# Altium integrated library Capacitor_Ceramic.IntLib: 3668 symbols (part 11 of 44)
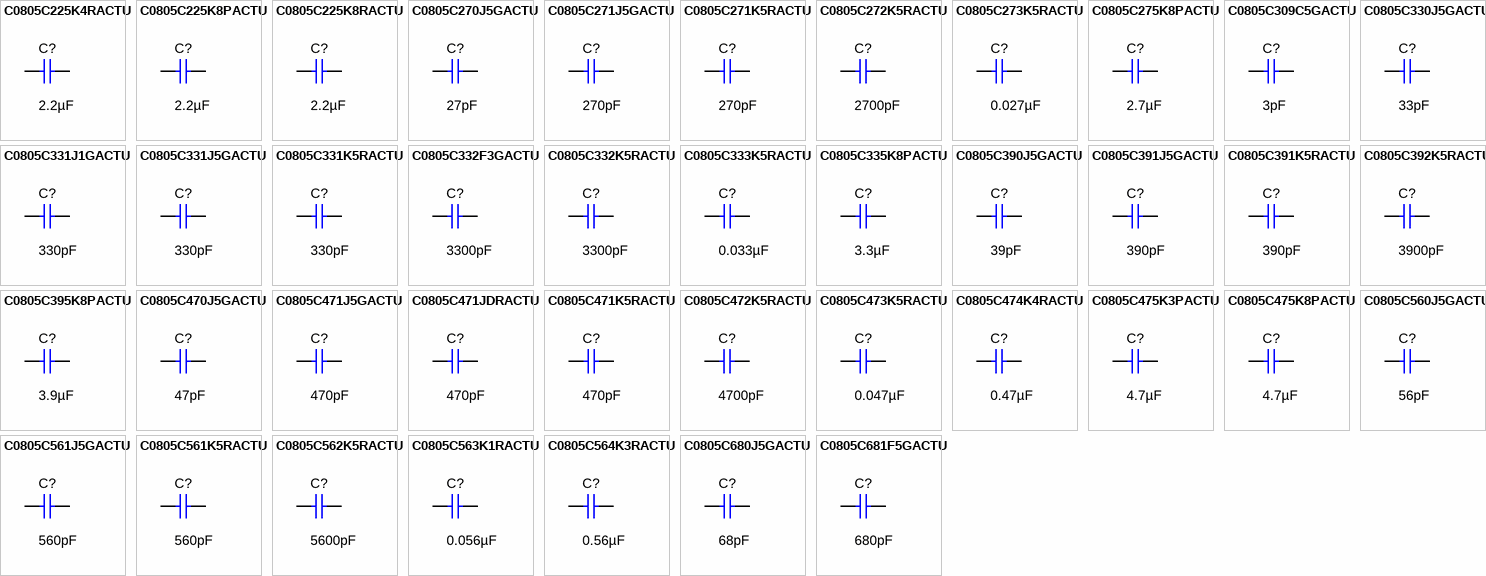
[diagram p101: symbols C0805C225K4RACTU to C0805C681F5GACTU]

## C0805C680J5GACTU
designator C?  ValueDisplayed: 68pF  (hidden comment: C0805C680J5GACTU)
CAP, CERM, 68 pF, 50 V,+/- 5%, C0G/NP0, 0805; Manufacturer: Kemet; Polarized: N; CompType: Capacitor; Value: 68pF; U/M: EA; Cap_F: 0.000000000068; Tolerance_%: 5; ESR_ohm: 0.094; Value1: 0.094 ohm; VDC_V: 50; Value2: 50V; IRMS_A: 0.603; TaMin_C: -55; TaMax_C: 125; Cap_Case: 0805; SizeArea_mm2: 2.5; SizeAreaWB_mm2: 6.75; SizeX_mm: 2; SizeY_mm: 1.25; SizeZ_mm: 1.45; AEC Category: Q200; Green_Lifecycle: Not Set; Green_REACh: Incomplete
signal-integrity model Cap
simulation model Cap
footprint 0805_HV
footprint 0805_HV1
footprint 0805
footprint 0805M
footprint 0805L
pins: 1, 2

## C0805C681F5GACTU
designator C?  ValueDisplayed: 680pF  (hidden comment: C0805C681F5GACTU)
CAP, CERM, 680 pF, 50 V,+/- 1%, C0G/NP0, 0805; Manufacturer: Kemet; Polarized: N; CompType: Capacitor; Value: 680pF; U/M: EA; Cap_F: 0.00000000068; Tolerance_%: 1; VDC_V: 50; Value2: 50V; TaMin_C: -55; TaMax_C: 125; Cap_Case: 0805; SizeArea_mm2: 2.5; SizeAreaWB_mm2: 6.75; SizeX_mm: 2; SizeY_mm: 1.25; SizeZ_mm: 1.45; AEC Category: Q200; Green_Lifecycle: Not Set; Green_REACh: Incomplete
signal-integrity model Cap
simulation model Cap
footprint 0805_HV
footprint 0805_HV1
footprint 0805
footprint 0805M
footprint 0805L
pins: 1, 2

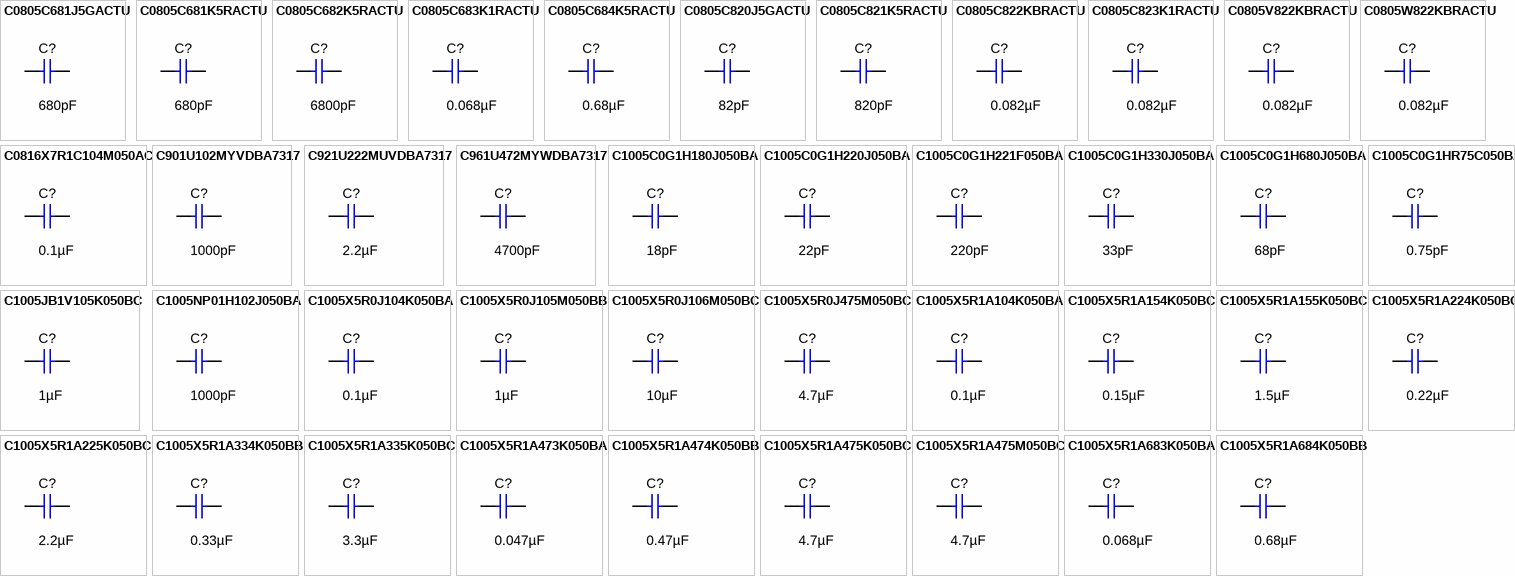
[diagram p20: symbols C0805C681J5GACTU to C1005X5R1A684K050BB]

## C0805C681J5GACTU
designator C?  ValueDisplayed: 680pF  (hidden comment: C0805C681J5GACTU)
CAP, CERM, 680 pF, 50 V,+/- 5%, C0G/NP0, 0805; Manufacturer: Kemet; Polarized: N; CompType: Capacitor; Value: 680pF; U/M: EA; Cap_F: 0.00000000068; Tolerance_%: 5; ESR_ohm: 0.027; Value1: 0.027 ohm; VDC_V: 50; Value2: 50V; IRMS_A: 1.38; TaMin_C: -55; TaMax_C: 125; Cap_Case: 0805; SizeArea_mm2: 2.5; SizeAreaWB_mm2: 6.75; SizeX_mm: 2; SizeY_mm: 1.25; SizeZ_mm: 1.45; AEC Category: Q200; Green_Lifecycle: Not Set; Green_REACh: Incomplete
signal-integrity model Cap
simulation model Cap
footprint 0805_HV
footprint 0805_HV1
footprint 0805
footprint 0805M
footprint 0805L
pins: 1, 2

## C0805C681K5RACTU
designator C?  ValueDisplayed: 680pF  (hidden comment: C0805C681K5RACTU)
CAP, CERM, 680 pF, 50 V,+/- 10%, X7R, 0805; Manufacturer: Kemet; Polarized: N; CompType: Capacitor; Value: 680pF; U/M: EA; Cap_F: 0.00000000068; Tolerance_%: 10; ESR_ohm: 0.478; Value1: 0.478 ohm; VDC_V: 50; Value2: 50V; IRMS_A: 0.188; TaMin_C: -55; TaMax_C: 125; Cap_Case: 0805; SizeArea_mm2: 2.5; SizeAreaWB_mm2: 6.75; SizeX_mm: 2; SizeY_mm: 1.25; SizeZ_mm: 1.45; AEC Category: Q200; Green_Lifecycle: Not Set; Green_REACh: Incomplete
signal-integrity model Cap
simulation model Cap
footprint 0805_HV
footprint 0805_HV1
footprint 0805
footprint 0805M
footprint 0805L
pins: 1, 2

## C0805C682K5RACTU
designator C?  ValueDisplayed: 6800pF  (hidden comment: C0805C682K5RACTU)
CAP, CERM, 6800 pF, 50 V,+/- 10%, X7R, 0805; Manufacturer: Kemet; Polarized: N; CompType: Capacitor; Value: 6800pF; U/M: EA; Cap_F: 0.0000000068; Tolerance_%: 10; ESR_ohm: 0.182; Value1: 0.182 ohm; VDC_V: 50; Value2: 50V; IRMS_A: 0.336; TaMin_C: -55; TaMax_C: 125; Cap_Case: 0805; SizeArea_mm2: 2.5; SizeAreaWB_mm2: 6.75; SizeX_mm: 2; SizeY_mm: 1.25; SizeZ_mm: 1.45; AEC Category: Q200; Green_Lifecycle: Not Set; Green_REACh: Incomplete
signal-integrity model Cap
simulation model Cap
footprint 0805_HV
footprint 0805_HV1
footprint 0805
footprint 0805M
footprint 0805L
pins: 1, 2

## C0805C683K1RACTU
designator C?  ValueDisplayed: 0.068µF  (hidden comment: C0805C683K1RACTU)
CAP, CERM, 0.068 µF, 100 V,+/- 10%, X7R, 0805; Manufacturer: Kemet; Polarized: N; CompType: Capacitor; Value: 0.068uF; U/M: EA; Cap_F: 0.000000068; Tolerance_%: 10; ESR_ohm: 0.078; Value1: 0.078 ohm; VDC_V: 100; Value2: 100V; IRMS_A: 1.28; TaMin_C: -55; TaMax_C: 125; Cap_Case: 0805; SizeArea_mm2: 2.5; SizeAreaWB_mm2: 6.75; SizeX_mm: 2; SizeY_mm: 1.25; SizeZ_mm: 1.45; AEC Category: Q200; Green_Lifecycle: Not Set; Green_REACh: Incomplete
signal-integrity model Cap
simulation model Cap
footprint 0805_HV
footprint 0805_HV1
footprint 0805
footprint 0805M
footprint 0805L
pins: 1, 2

## C0805C684K5RACTU
designator C?  ValueDisplayed: 0.68µF  (hidden comment: C0805C684K5RACTU)
CAP, CERM, 0.68 µF, 50 V,+/- 10%, X7R, 0805; Manufacturer: Kemet; Polarized: N; CompType: Capacitor; Value: 0.68uF; U/M: EA; Cap_F: 0.00000068; Tolerance_%: 10; VDC_V: 50; Value2: 50V; TaMin_C: -55; TaMax_C: 125; Cap_Case: 0805; SizeArea_mm2: 2.5; SizeAreaWB_mm2: 6.75; SizeX_mm: 2; SizeY_mm: 1.25; SizeZ_mm: 1.45; AEC Category: Q200; Green_Lifecycle: Active; Green_REACh: Passed
signal-integrity model Cap
simulation model Cap
footprint 0805_HV
footprint 0805_HV1
footprint 0805
footprint 0805M
footprint 0805L
pins: 1, 2

## C0805C820J5GACTU
designator C?  ValueDisplayed: 82pF  (hidden comment: C0805C820J5GACTU)
CAP, CERM, 82 pF, 50 V,+/- 5%, C0G/NP0, 0805; Manufacturer: Kemet; Polarized: N; CompType: Capacitor; Value: 82pF; U/M: EA; Cap_F: 0.000000000082; Tolerance_%: 5; ESR_ohm: 0.084; Value1: 0.084 ohm; VDC_V: 50; Value2: 50V; IRMS_A: 0.677; TaMin_C: -55; TaMax_C: 125; Cap_Case: 0805; SizeArea_mm2: 2.5; SizeAreaWB_mm2: 6.75; SizeX_mm: 2; SizeY_mm: 1.25; SizeZ_mm: 1.45; AEC Category: Q200; Green_Lifecycle: Active; Green_REACh: Passed
signal-integrity model Cap
simulation model Cap
footprint 0805_HV
footprint 0805_HV1
footprint 0805
footprint 0805M
footprint 0805L
pins: 1, 2

## C0805C821K5RACTU
designator C?  ValueDisplayed: 820pF  (hidden comment: C0805C821K5RACTU)
CAP, CERM, 820 pF, 50 V,+/- 10%, X7R, 0805; Manufacturer: Kemet; Polarized: N; CompType: Capacitor; Value: 820pF; U/M: EA; Cap_F: 0.00000000082; Tolerance_%: 10; ESR_ohm: 0.425; Value1: 0.425 ohm; VDC_V: 50; Value2: 50V; IRMS_A: 0.204; TaMin_C: -55; TaMax_C: 125; Cap_Case: 0805; SizeArea_mm2: 2.5; SizeAreaWB_mm2: 6.75; SizeX_mm: 2; SizeY_mm: 1.25; SizeZ_mm: 1.45; AEC Category: Q200; Green_Lifecycle: Not Set; Green_REACh: Incomplete
signal-integrity model Cap
simulation model Cap
footprint 0805_HV
footprint 0805_HV1
footprint 0805
footprint 0805M
footprint 0805L
pins: 1, 2

## C0805C822KBRACTU
designator C?  ValueDisplayed: 0.082µF  (hidden comment: C0805C822KBRACTU)
CAP, CERM, 0.082 µF, 630 V,+/- 10%, X7R, 0805; Manufacturer: Kemet; Polarized: N; CompType: Capacitor; Value: 0.082uF; U/M: EA; Cap_F: 0.000000082; Tolerance_%: 10; VDC_V: 630; Value2: 630V; TaMin_C: -55; TaMax_C: 125; Cap_Case: 0805; SizeArea_mm2: 2.5; SizeAreaWB_mm2: 6.75; SizeX_mm: 2; SizeY_mm: 1.25; SizeZ_mm: 1.45; AEC Category: Q200; Green_Lifecycle: Not Set; Green_REACh: Incomplete
signal-integrity model Cap
simulation model Cap
footprint 0805_HV
footprint 0805_HV1
footprint 0805
footprint 0805M
footprint 0805L
pins: 1, 2

## C0805C823K1RACTU
designator C?  ValueDisplayed: 0.082µF  (hidden comment: C0805C823K1RACTU)
CAP, CERM, 0.082 µF, 100 V,+/- 10%, X7R, 0805; Manufacturer: Kemet; Polarized: N; CompType: Capacitor; Value: 0.082uF; U/M: EA; Cap_F: 0.000000082; Tolerance_%: 10; ESR_ohm: 0.071; Value1: 0.071 ohm; VDC_V: 100; Value2: 100V; IRMS_A: 1.44; TaMin_C: -55; TaMax_C: 125; Cap_Case: 0805; SizeArea_mm2: 2.5; SizeAreaWB_mm2: 6.75; SizeX_mm: 2; SizeY_mm: 1.25; SizeZ_mm: 1.45; AEC Category: Q200; Green_Lifecycle: Not Set; Green_REACh: Incomplete
signal-integrity model Cap
simulation model Cap
footprint 0805_HV
footprint 0805_HV1
footprint 0805
footprint 0805M
footprint 0805L
pins: 1, 2

## C0805V822KBRACTU
designator C?  ValueDisplayed: 0.082µF  (hidden comment: C0805V822KBRACTU)
CAP, CERM, 0.082 µF, 630 V,+/- 10%, X7R, 0805; Manufacturer: Kemet; Polarized: N; CompType: Capacitor; Value: 0.082uF; U/M: EA; Cap_F: 0.000000082; Tolerance_%: 10; VDC_V: 630; Value2: 630V; TaMin_C: -55; TaMax_C: 125; Cap_Case: 0805; SizeArea_mm2: 2.5; SizeAreaWB_mm2: 6.75; SizeX_mm: 2; SizeY_mm: 1.25; SizeZ_mm: 1.45; AEC Category: Q200; Green_Lifecycle: Not Set; Green_REACh: Incomplete
signal-integrity model Cap
simulation model Cap
footprint 0805_HV
footprint 0805_HV1
footprint 0805
footprint 0805M
footprint 0805L
pins: 1, 2

## C0805W822KBRACTU
designator C?  ValueDisplayed: 0.082µF  (hidden comment: C0805W822KBRACTU)
CAP, CERM, 0.082 µF, 630 V,+/- 10%, X7R, 0805; Manufacturer: Kemet; Polarized: N; CompType: Capacitor; Value: 0.082uF; U/M: EA; Cap_F: 0.000000082; Tolerance_%: 10; VDC_V: 630; Value2: 630V; TaMin_C: -55; TaMax_C: 125; Cap_Case: 0805; SizeArea_mm2: 2.5; SizeAreaWB_mm2: 6.75; SizeX_mm: 2; SizeY_mm: 1.25; SizeZ_mm: 1.45; AEC Category: Q200; Green_Lifecycle: Not Set; Green_REACh: Incomplete
signal-integrity model Cap
simulation model Cap
footprint 0805_HV
footprint 0805_HV1
footprint 0805
footprint 0805M
footprint 0805L
pins: 1, 2

## C0816X7R1C104M050AC
designator C?  ValueDisplayed: 0.1µF  (hidden comment: C0816X7R1C104M050AC)
CAP, CERM, 0.1 µF, 16 V,+/- 20%, X7R, 0306; Manufacturer: TDK; Polarized: N; CompType: Capacitor; Value: 0.1uF; U/M: EA; Cap_F: 0.0000001; Tolerance_%: 20; VDC_V: 16; Value2: 16V; TaMin_C: -55; TaMax_C: 125; Cap_Case: 0306; SizeArea_mm2: 1.28; SizeAreaWB_mm2: 4.68; SizeX_mm: 0.8; SizeY_mm: 1.6; SizeZ_mm: 0.6; AEC Category: Q200; Green_Lifecycle: Not Set; Green_REACh: Incomplete
signal-integrity model Cap
simulation model Cap
footprint 0306
pins: 1, 2

## C901U102MYVDBA7317
designator C?  ValueDisplayed: 1000pF  (hidden comment: C901U102MYVDBA7317)
CAP, CERM, 1000 pF, X1 400 VAC/Y2 250 VAC, +/- 20%, Y5V, D7xT5mm; Manufacturer: Kemet; Polarized: N; CompType: Capacitor; Value: 1000pF; U/M: EA; Cap_F: 0.000000001; Tolerance_%: 20; TaMin_C: -40; TaMax_C: 125; Cap_Case: 7x5mm; SizeArea_mm2: 55; SizeAreaWB_mm2: 91; SizeX_mm: 11; SizeY_mm: 5; AEC Category: Q200; Green_Lifecycle: Not Set; Green_REACh: Incomplete; AC_Safety: X1Y2; VAC_X: 400; VAC_Y: 250
signal-integrity model Cap
simulation model Cap
footprint C901_B
pins: 1, 2

## C921U222MUVDBA7317
designator C?  ValueDisplayed: 2.2µF  (hidden comment: C921U222MUVDBA7317)
CAP, CERM, 2.2 µF, X1 400 VAC/Y1 250 VAC, +/- 20%, Y5V, Cap 9x13mm; Manufacturer: Kemet; Polarized: N; CompType: Capacitor; Value: 2.2uF; U/M: EA; Cap_F: 0.0000022; Tolerance_%: 20; TaMin_C: -25; TaMax_C: 125; Cap_Case: C921_5500T_VertKink; SizeArea_mm2: 45; SizeAreaWB_mm2: 77; SizeX_mm: 9; SizeY_mm: 5; SizeZ_mm: 14; AEC Category: Q200; AC_Safety: X1Y1; VAC_X: 400; VAC_Y: 250
signal-integrity model Cap
simulation model Cap
footprint C921_5500T_VertKink
pins: 1, 2

## C961U472MYWDBA7317
designator C?  ValueDisplayed: 4700pF  (hidden comment: C961U472MYWDBA7317)
CAP, CERM, 4700 pF, X1 400 VAC/Y2 250 VAC, +/- 20%, Y5U, 13x5mm; Manufacturer: Kemet; Polarized: N; CompType: Capacitor; Value: 4700pF; U/M: EA; Cap_F: 0.0000000047; Tolerance_%: 20; TaMin_C: -40; TaMax_C: 125; SizeArea_mm2: 65; SizeAreaWB_mm2: 105; SizeX_mm: 13; SizeY_mm: 5; SizeZ_mm: 17; AEC Category: Q200; AC_Safety: X1Y2; VAC_X: 400; VAC_Y: 250
signal-integrity model Cap
simulation model Cap
footprint C961_B
pins: 1, 2

## C1005C0G1H180J050BA
designator C?  ValueDisplayed: 18pF  (hidden comment: C1005C0G1H180J050BA)
CAP, CERM, 18 pF, 50 V,+/- 5%, C0G/NP0, 0402; Manufacturer: TDK; Polarized: N; CompType: Capacitor; Value: 18pF; U/M: EA; Cap_F: 0.000000000018; Tolerance_%: 5; VDC_V: 50; Value2: 50V; TaMin_C: -55; TaMax_C: 125; Cap_Case: 0402; SizeArea_mm2: 0.5; SizeAreaWB_mm2: 3; SizeX_mm: 1; SizeZ_mm: 0.6; AEC Category: Q200; Green_Lifecycle: Not Set; Green_REACh: Incomplete
signal-integrity model Cap
simulation model Cap
footprint 0402
footprint 0402M
footprint 0402L
footprint 0402S
pins: 1, 2

## C1005C0G1H220J050BA
designator C?  ValueDisplayed: 22pF  (hidden comment: C1005C0G1H220J050BA)
CAP, CERM, 22 pF, 50 V,+/- 5%, C0G/NP0, 0402; Manufacturer: TDK; Polarized: N; CompType: Capacitor; Value: 22pF; U/M: EA; Cap_F: 0.000000000022; Tolerance_%: 5; VDC_V: 50; Value2: 50V; TaMin_C: -55; TaMax_C: 125; Cap_Case: 0402; SizeArea_mm2: 0.5; SizeAreaWB_mm2: 3; SizeX_mm: 1; SizeZ_mm: 0.6; AEC Category: Q200; Green_Lifecycle: NRND; Green_REACh: Passed
signal-integrity model Cap
simulation model Cap
footprint 0402
footprint 0402M
footprint 0402L
footprint 0402S
pins: 1, 2

## C1005C0G1H221F050BA
designator C?  ValueDisplayed: 220pF  (hidden comment: C1005C0G1H221F050BA)
CAP, CERM, 220 pF, 50 V,+/- 1%, C0G/NP0, 0402; Manufacturer: TDK; Polarized: N; CompType: Capacitor; Value: 220pF; U/M: EA; Cap_F: 0.00000000022; Tolerance_%: 1; VDC_V: 50; Value2: 50V; TaMin_C: -55; TaMax_C: 125; Cap_Case: 0402; SizeArea_mm2: 0.5; SizeAreaWB_mm2: 3; SizeZ_mm: 0.6; AEC Category: Q200; Green_Lifecycle: NRND; Green_REACh: Passed
signal-integrity model Cap
simulation model Cap
footprint 0402
footprint 0402M
footprint 0402L
footprint 0402S
pins: 1, 2

## C1005C0G1H330J050BA
designator C?  ValueDisplayed: 33pF  (hidden comment: C1005C0G1H330J050BA)
CAP, CERM, 33 pF, 50 V,+/- 5%, C0G/NP0, 0402; Manufacturer: TDK; Polarized: N; CompType: Capacitor; Value: 33pF; U/M: EA; Cap_F: 0.000000000033; Tolerance_%: 5; VDC_V: 50; Value2: 50V; TaMin_C: -55; TaMax_C: 125; Cap_Case: 0402; SizeArea_mm2: 0.5; SizeAreaWB_mm2: 3; SizeX_mm: 1; SizeZ_mm: 0.6; AEC Category: Q200; Green_Lifecycle: Not Set; Green_REACh: Incomplete
signal-integrity model Cap
simulation model Cap
footprint 0402
footprint 0402M
footprint 0402L
footprint 0402S
pins: 1, 2

## C1005C0G1H680J050BA
designator C?  ValueDisplayed: 68pF  (hidden comment: C1005C0G1H680J050BA)
CAP, CERM, 68 pF, 50 V,+/- 5%, C0G/NP0, 0402; Manufacturer: TDK; Polarized: N; CompType: Capacitor; Value: 68pF; U/M: EA; Cap_F: 0.000000000068; Tolerance_%: 5; VDC_V: 50; Value2: 50V; TaMin_C: -55; TaMax_C: 125; Cap_Case: 0402; SizeArea_mm2: 0.5; SizeAreaWB_mm2: 3; SizeX_mm: 1; SizeZ_mm: 0.6; AEC Category: Q200; Green_Lifecycle: Not Set; Green_REACh: Incomplete
signal-integrity model Cap
simulation model Cap
footprint 0402
footprint 0402M
footprint 0402L
footprint 0402S
pins: 1, 2

## C1005C0G1HR75C050BA
designator C?  ValueDisplayed: 0.75pF  (hidden comment: C1005C0G1HR75C050BA)
CAP, CERM, 0.75pF, 50 V,+/- 33%, C0G/NP0, 0402; Manufacturer: TDK; Polarized: N; CompType: Capacitor; U/M: EA; Cap_F: 0.00000000000075; Tolerance_%: 33; VDC_V: 50; Value2: 50V; TaMin_C: -55; TaMax_C: 125; Cap_Case: 0402; SizeArea_mm2: 0.5; SizeAreaWB_mm2: 3; SizeX_mm: 1; SizeZ_mm: 0.6; AEC Category: Q200
signal-integrity model Cap
simulation model Cap
footprint 0402
footprint 0402M
footprint 0402L
footprint 0402S
pins: 1, 2

## C1005JB1V105K050BC
designator C?  ValueDisplayed: 1µF  (hidden comment: C1005JB1V105K050BC)
CAP, CERM, 1 µF, 35 V,+/- 10%, JB, 0402; Manufacturer: TDK; Polarized: N; CompType: Capacitor; Value: 1uF; U/M: EA; Cap_F: 0.000001; Tolerance_%: 10; VDC_V: 35; Value2: 35V; TaMin_C: -25; TaMax_C: 85; Cap_Case: 0402; SizeArea_mm2: 0.5; SizeAreaWB_mm2: 3; SizeX_mm: 1; SizeZ_mm: 0.6; AEC Category: Q200; Green_Lifecycle: Active; Green_REACh: Passed
signal-integrity model Cap
simulation model Cap
footprint 0402
footprint 0402M
footprint 0402L
footprint 0402S
pins: 1, 2

## C1005NP01H102J050BA
designator C?  ValueDisplayed: 1000pF  (hidden comment: C1005NP01H102J050BA)
CAP, CERM, 1000 pF, 50 V,+/- 5%, C0G/NP0, 0402; Manufacturer: TDK; Polarized: N; CompType: Capacitor; Value: 1000pF; U/M: EA; Cap_F: 0.000000001; Tolerance_%: 5; VDC_V: 50; Value2: 50V; TaMin_C: -55; TaMax_C: 150; Cap_Case: 0402; SizeArea_mm2: 0.5; SizeAreaWB_mm2: 3; SizeX_mm: 1; SizeZ_mm: 0.6; AEC Category: Q200; Green_Lifecycle: Not Set; Green_REACh: Incomplete
signal-integrity model Cap
simulation model Cap
footprint 0402
footprint 0402M
footprint 0402L
footprint 0402S
pins: 1, 2

## C1005X5R0J104K050BA
designator C?  ValueDisplayed: 0.1µF  (hidden comment: C1005X5R0J104K050BA)
CAP, CERM, 0.1 µF, 6.3 V,+/- 10%, X5R, 0402; Manufacturer: TDK; Polarized: N; CompType: Capacitor; Value: 0.1uF; U/M: EA; Cap_F: 0.0000001; Tolerance_%: 10; ESR_ohm: 0.0186; Value1: 0.0186 ohm; VDC_V: 6.3; Value2: 6.3V; TaMin_C: -55; TaMax_C: 85; Cap_Case: 0402; SizeArea_mm2: 0.5; SizeAreaWB_mm2: 3; SizeX_mm: 1; SizeZ_mm: 0.6; AEC Category: Q200; Green_Lifecycle: NRND; Green_REACh: Passed
signal-integrity model Cap
simulation model Cap
footprint 0402
footprint 0402M
footprint 0402L
footprint 0402S
pins: 1, 2

## C1005X5R0J105M050BB
designator C?  ValueDisplayed: 1µF  (hidden comment: C1005X5R0J105M050BB)
CAP, CERM, 1 µF, 6.3 V,+/- 20%, X5R, 0402; Manufacturer: TDK; Polarized: N; CompType: Capacitor; Value: 1uF; U/M: EA; Cap_F: 0.000001; Tolerance_%: 20; ESR_ohm: 0.0079; Value1: 0.0079 ohm; VDC_V: 6.3; Value2: 6.3V; TaMin_C: -55; TaMax_C: 85; Cap_Case: 0402; SizeArea_mm2: 0.5; SizeAreaWB_mm2: 3; SizeX_mm: 1; SizeZ_mm: 0.6; AEC Category: Q200; Green_Lifecycle: EOL; Green_REACh: Passed
signal-integrity model Cap
simulation model Cap
footprint 0402
footprint 0402M
footprint 0402L
footprint 0402S
pins: 1, 2

## C1005X5R0J106M050BC
designator C?  ValueDisplayed: 10µF  (hidden comment: C1005X5R0J106M050BC)
CAP, CERM, 10 µF, 6.3 V,+/- 20%, X5R, 0402; Manufacturer: TDK; Polarized: N; CompType: Capacitor; Value: 10uF; U/M: EA; Cap_F: 0.00001; Tolerance_%: 20; ESR_ohm: 0.003019; Value1: 0.003019 ohm; VDC_V: 6.3; Value2: 6.3V; IRMS_A: 2.87803; TaMin_C: -55; TaMax_C: 85; Cap_Case: 0402; SizeArea_mm2: 0.5; SizeAreaWB_mm2: 3; SizeX_mm: 1; SizeZ_mm: 0.7; AEC Category: Q200; Green_Lifecycle: Active; Green_REACh: Passed
signal-integrity model Cap
simulation model Cap
footprint 0402_070
pins: 1, 2

## C1005X5R0J475M050BC
designator C?  ValueDisplayed: 4.7µF  (hidden comment: C1005X5R0J475M050BC)
CAP, CERM, 4.7 µF, 6.3 V,+/- 20%, X5R, 0402; Manufacturer: TDK; Polarized: N; CompType: Capacitor; Value: 4.7uF; U/M: EA; Cap_F: 0.0000047; Tolerance_%: 20; VDC_V: 6.3; Value2: 6.3V; TaMin_C: -55; TaMax_C: 85; Cap_Case: 0402; SizeArea_mm2: 0.5; SizeAreaWB_mm2: 3; SizeX_mm: 1; SizeZ_mm: 0.6; AEC Category: Q200; Green_Lifecycle: Active; Green_REACh: Passed
signal-integrity model Cap
simulation model Cap
footprint 0402
footprint 0402M
footprint 0402L
footprint 0402S
pins: 1, 2

## C1005X5R1A104K050BA
designator C?  ValueDisplayed: 0.1µF  (hidden comment: C1005X5R1A104K050BA)
CAP, CERM, 0.1 µF, 10 V,+/- 10%, X5R, 0402; Manufacturer: TDK; Polarized: N; CompType: Capacitor; Value: 0.1uF; U/M: EA; Cap_F: 0.0000001; Tolerance_%: 10; Value2: 10V; TaMin_C: -55; TaMax_C: 85; Cap_Case: 0402; SizeArea_mm2: 0.5; SizeAreaWB_mm2: 3; SizeX_mm: 1; SizeZ_mm: 0.6; AEC Category: Q200; Green_Lifecycle: NRND; Green_REACh: Passed
signal-integrity model Cap
simulation model Cap
footprint 0402
footprint 0402M
footprint 0402L
footprint 0402S
pins: 1, 2

## C1005X5R1A154K050BC
designator C?  ValueDisplayed: 0.15µF  (hidden comment: C1005X5R1A154K050BC)
CAP, CERM, 0.15 µF, 10 V,+/- 10%, X5R, 0402; Manufacturer: TDK; Polarized: N; CompType: Capacitor; Value: 0.15uF; U/M: EA; Cap_F: 0.00000015; Tolerance_%: 10; Value2: 10V; TaMin_C: -55; TaMax_C: 85; Cap_Case: 0402; SizeArea_mm2: 0.5; SizeAreaWB_mm2: 3; SizeX_mm: 1; SizeZ_mm: 0.6; AEC Category: Q200; Green_Lifecycle: EOL; Green_REACh: Passed
signal-integrity model Cap
simulation model Cap
footprint 0402
footprint 0402M
footprint 0402L
footprint 0402S
pins: 1, 2

## C1005X5R1A155K050BC
designator C?  ValueDisplayed: 1.5µF  (hidden comment: C1005X5R1A155K050BC)
CAP, CERM, 1.5 µF, 10 V,+/- 10%, X5R, 0402; Manufacturer: TDK; Polarized: N; CompType: Capacitor; Value: 1.5uF; U/M: EA; Cap_F: 0.0000015; Tolerance_%: 10; Value2: 10V; TaMin_C: -55; TaMax_C: 85; Cap_Case: 0402; SizeArea_mm2: 0.5; SizeAreaWB_mm2: 3; SizeX_mm: 1; SizeZ_mm: 0.6; AEC Category: Q200; Green_Lifecycle: Active; Green_REACh: Passed
signal-integrity model Cap
simulation model Cap
footprint 0402
footprint 0402M
footprint 0402L
footprint 0402S
pins: 1, 2

## C1005X5R1A224K050BC
designator C?  ValueDisplayed: 0.22µF  (hidden comment: C1005X5R1A224K050BC)
CAP, CERM, 0.22 µF, 10 V,+/- 10%, X5R, 0402; Manufacturer: TDK; Polarized: N; CompType: Capacitor; Value: 0.22uF; U/M: EA; Cap_F: 0.00000022; Tolerance_%: 10; Value2: 10V; TaMin_C: -55; TaMax_C: 85; Cap_Case: 0402; SizeArea_mm2: 0.5; SizeAreaWB_mm2: 3; SizeX_mm: 1; SizeZ_mm: 0.6; AEC Category: Q200
signal-integrity model Cap
simulation model Cap
footprint 0402
footprint 0402M
footprint 0402L
footprint 0402S
pins: 1, 2

## C1005X5R1A225K050BC
designator C?  ValueDisplayed: 2.2µF  (hidden comment: C1005X5R1A225K050BC)
CAP, CERM, 2.2 µF, 10 V,+/- 10%, X5R, 0402; Manufacturer: TDK; Polarized: N; CompType: Capacitor; Value: 2.2uF; U/M: EA; Cap_F: 0.0000022; Tolerance_%: 10; Value2: 10V; TaMin_C: -55; TaMax_C: 85; Cap_Case: 0402; SizeArea_mm2: 0.5; SizeAreaWB_mm2: 3; SizeX_mm: 1; SizeZ_mm: 0.6; AEC Category: Q200; Green_Lifecycle: Active; Green_REACh: Passed
signal-integrity model Cap
simulation model Cap
footprint 0402
footprint 0402M
footprint 0402L
footprint 0402S
pins: 1, 2

## C1005X5R1A334K050BB
designator C?  ValueDisplayed: 0.33µF  (hidden comment: C1005X5R1A334K050BB)
CAP, CERM, 0.33 µF, 10 V,+/- 10%, X5R, 0402; Manufacturer: TDK; Polarized: N; CompType: Capacitor; Value: 0.33uF; U/M: EA; Cap_F: 0.00000033; Tolerance_%: 10; Value2: 10V; TaMin_C: -55; TaMax_C: 85; Cap_Case: 0402; SizeArea_mm2: 0.5; SizeAreaWB_mm2: 3; SizeX_mm: 1; SizeZ_mm: 0.6; AEC Category: Q200; Green_Lifecycle: EOL; Green_REACh: Passed
signal-integrity model Cap
simulation model Cap
footprint 0402
footprint 0402M
footprint 0402L
footprint 0402S
pins: 1, 2

## C1005X5R1A335K050BC
designator C?  ValueDisplayed: 3.3µF  (hidden comment: C1005X5R1A335K050BC)
CAP, CERM, 3.3 µF, 10 V,+/- 10%, X5R, 0402; Manufacturer: TDK; Polarized: N; CompType: Capacitor; Value: 3.3uF; U/M: EA; Cap_F: 0.0000033; Tolerance_%: 10; ESR_ohm: 0.004157; Value1: 0.004157 ohm; Value2: 10V; IRMS_A: 2.45391; TaMin_C: -55; TaMax_C: 85; Cap_Case: 0402; SizeArea_mm2: 0.5; SizeAreaWB_mm2: 3; SizeX_mm: 1; SizeZ_mm: 0.6; AEC Category: Q200
signal-integrity model Cap
simulation model Cap
footprint 0402
footprint 0402M
footprint 0402L
footprint 0402S
pins: 1, 2

## C1005X5R1A473K050BA
designator C?  ValueDisplayed: 0.047µF  (hidden comment: C1005X5R1A473K050BA)
CAP, CERM, 0.047 µF, 10 V,+/- 10%, X5R, 0402; Manufacturer: TDK; Polarized: N; CompType: Capacitor; Value: 0.047uF; U/M: EA; Cap_F: 0.000000047; Tolerance_%: 10; Value2: 10V; TaMin_C: -55; TaMax_C: 85; Cap_Case: 0402; SizeArea_mm2: 0.5; SizeAreaWB_mm2: 3; SizeX_mm: 1; SizeZ_mm: 0.6; AEC Category: Q200; Green_Lifecycle: NRND; Green_REACh: Passed
signal-integrity model Cap
simulation model Cap
footprint 0402
footprint 0402M
footprint 0402L
footprint 0402S
pins: 1, 2

## C1005X5R1A474K050BB
designator C?  ValueDisplayed: 0.47µF  (hidden comment: C1005X5R1A474K050BB)
CAP, CERM, 0.47 µF, 10 V,+/- 10%, X5R, 0402; Manufacturer: TDK; Polarized: N; CompType: Capacitor; Value: 0.47uF; U/M: EA; Cap_F: 0.00000047; Tolerance_%: 10; Value2: 10V; TaMin_C: -55; TaMax_C: 85; Cap_Case: 0402; SizeArea_mm2: 0.5; SizeAreaWB_mm2: 3; SizeX_mm: 1; SizeZ_mm: 0.6; AEC Category: Q200; Green_Lifecycle: EOL; Green_REACh: Passed
signal-integrity model Cap
simulation model Cap
footprint 0402
footprint 0402M
footprint 0402L
footprint 0402S
pins: 1, 2

## C1005X5R1A475K050BC
designator C?  ValueDisplayed: 4.7µF  (hidden comment: C1005X5R1A475K050BC)
CAP, CERM, 4.7 µF, 10 V,+/- 10%, X5R, 0402; Manufacturer: TDK; Polarized: N; CompType: Capacitor; Value: 4.7uF; U/M: EA; Cap_F: 0.0000047; Tolerance_%: 10; ESR_ohm: 0.003417; Value1: 0.003417 ohm; Value2: 10V; IRMS_A: 2.7063; TaMin_C: -55; TaMax_C: 85; Cap_Case: 0402; SizeArea_mm2: 0.5; SizeAreaWB_mm2: 3; SizeX_mm: 1; SizeZ_mm: 0.65; AEC Category: Q200; Green_Lifecycle: Active; Green_REACh: Passed
signal-integrity model Cap
simulation model Cap
footprint 0402_065
footprint 0402_065M
footprint 0402_065L
footprint 0402_065S
pins: 1, 2

## C1005X5R1A475M050BC
designator C?  ValueDisplayed: 4.7µF  (hidden comment: C1005X5R1A475M050BC)
CAP, CERM, 4.7 µF, 10 V,+/- 20%, X5R, 0402; Manufacturer: TDK; Polarized: N; CompType: Capacitor; Value: 4.7uF; U/M: EA; Cap_F: 0.0000047; Tolerance_%: 20; VDC_V: 10; Value2: 10V; TaMin_C: -55; TaMax_C: 85; Cap_Case: 0402; SizeArea_mm2: 0.5; SizeAreaWB_mm2: 3; SizeX_mm: 1; SizeZ_mm: 0.6; AEC Category: Q200; Green_Lifecycle: Active; Green_REACh: Passed
signal-integrity model Cap
simulation model Cap
footprint 0402
footprint 0402M
footprint 0402L
footprint 0402S
pins: 1, 2

## C1005X5R1A683K050BA
designator C?  ValueDisplayed: 0.068µF  (hidden comment: C1005X5R1A683K050BA)
CAP, CERM, 0.068 µF, 10 V,+/- 10%, X5R, 0402; Manufacturer: TDK; Polarized: N; CompType: Capacitor; Value: 0.068uF; U/M: EA; Cap_F: 0.000000068; Tolerance_%: 10; Value2: 10V; TaMin_C: -55; TaMax_C: 85; Cap_Case: 0402; SizeArea_mm2: 0.5; SizeAreaWB_mm2: 3; SizeX_mm: 1; SizeZ_mm: 0.6; AEC Category: Q200
signal-integrity model Cap
simulation model Cap
footprint 0402
footprint 0402M
footprint 0402L
footprint 0402S
pins: 1, 2

## C1005X5R1A684K050BB
designator C?  ValueDisplayed: 0.68µF  (hidden comment: C1005X5R1A684K050BB)
CAP, CERM, 0.68 µF, 10 V,+/- 10%, X5R, 0402; Manufacturer: TDK; Polarized: N; CompType: Capacitor; Value: 0.68uF; U/M: EA; Cap_F: 0.00000068; Tolerance_%: 10; Value2: 10V; TaMin_C: -55; TaMax_C: 85; Cap_Case: 0402; SizeArea_mm2: 0.5; SizeAreaWB_mm2: 3; SizeX_mm: 1; SizeZ_mm: 0.6; AEC Category: Q200
signal-integrity model Cap
simulation model Cap
footprint 0402
footprint 0402M
footprint 0402L
footprint 0402S
pins: 1, 2

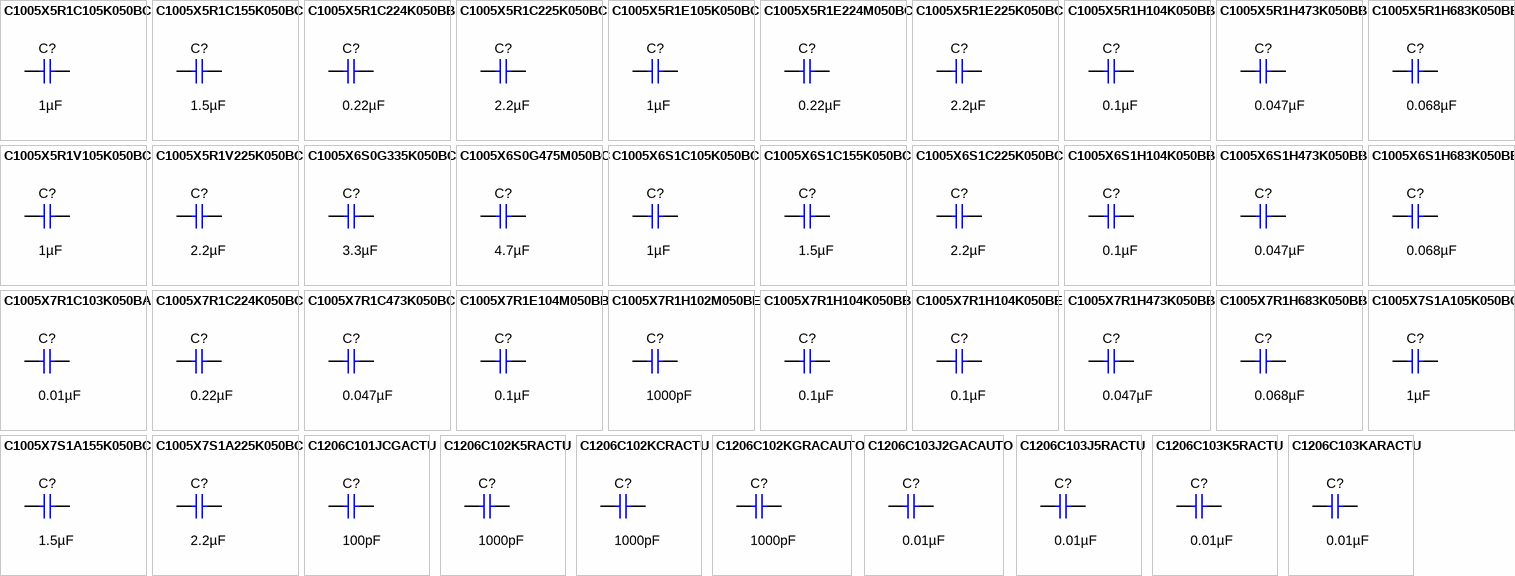
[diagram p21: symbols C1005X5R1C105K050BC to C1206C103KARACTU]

## C1005X5R1C105K050BC
designator C?  ValueDisplayed: 1µF  (hidden comment: C1005X5R1C105K050BC)
CAP, CERM, 1 µF, 16 V,+/- 10%, X5R, 0402; Manufacturer: TDK; Polarized: N; CompType: Capacitor; Value: 1uF; U/M: EA; Cap_F: 0.000001; Tolerance_%: 10; VDC_V: 16; Value2: 16V; TaMin_C: -55; TaMax_C: 85; Cap_Case: 0402; SizeArea_mm2: 0.5; SizeAreaWB_mm2: 3; SizeX_mm: 1; SizeZ_mm: 0.6; AEC Category: Q200; Green_Lifecycle: EOL; Green_REACh: Passed
signal-integrity model Cap
simulation model Cap
footprint 0402
footprint 0402M
footprint 0402L
footprint 0402S
pins: 1, 2

## C1005X5R1C155K050BC
designator C?  ValueDisplayed: 1.5µF  (hidden comment: C1005X5R1C155K050BC)
CAP, CERM, 1.5 µF, 16 V,+/- 10%, X5R, 0402; Manufacturer: TDK; Polarized: N; CompType: Capacitor; Value: 1.5uF; U/M: EA; Cap_F: 0.0000015; Tolerance_%: 10; ESR_ohm: 0.007753; Value1: 0.007753 ohm; VDC_V: 16; Value2: 16V; IRMS_A: 1.79804; TaMin_C: -55; TaMax_C: 85; Cap_Case: 0402; SizeArea_mm2: 0.5; SizeAreaWB_mm2: 3; SizeX_mm: 1; SizeZ_mm: 0.6; AEC Category: Q200
signal-integrity model Cap
simulation model Cap
footprint 0402
footprint 0402M
footprint 0402L
footprint 0402S
pins: 1, 2

## C1005X5R1C224K050BB
designator C?  ValueDisplayed: 0.22µF  (hidden comment: C1005X5R1C224K050BB)
CAP, CERM, 0.22 µF, 16 V,+/- 10%, X5R, 0402; Manufacturer: TDK; Polarized: N; CompType: Capacitor; Value: 0.22uF; U/M: EA; Cap_F: 0.00000022; Tolerance_%: 10; VDC_V: 16; Value2: 16V; TaMin_C: -55; TaMax_C: 85; Cap_Case: 0402; SizeArea_mm2: 0.5; SizeAreaWB_mm2: 3; SizeX_mm: 1; SizeZ_mm: 0.6; AEC Category: Q200; Green_Lifecycle: Not Set; Green_REACh: Incomplete
signal-integrity model Cap
simulation model Cap
footprint 0402
footprint 0402M
footprint 0402L
footprint 0402S
pins: 1, 2

## C1005X5R1C225K050BC
designator C?  ValueDisplayed: 2.2µF  (hidden comment: C1005X5R1C225K050BC)
CAP, CERM, 2.2 µF, 16 V,+/- 10%, X5R, 0402; Manufacturer: TDK; Polarized: N; CompType: Capacitor; Value: 2.2uF; U/M: EA; Cap_F: 0.0000022; Tolerance_%: 10; VDC_V: 16; Value2: 16V; TaMin_C: -55; TaMax_C: 85; Cap_Case: 0402; SizeArea_mm2: 0.5; SizeAreaWB_mm2: 3; SizeX_mm: 1; SizeZ_mm: 0.6; AEC Category: Q200; Green_Lifecycle: Active; Green_REACh: Passed
signal-integrity model Cap
simulation model Cap
footprint 0402
footprint 0402M
footprint 0402L
footprint 0402S
pins: 1, 2

## C1005X5R1E105K050BC
designator C?  ValueDisplayed: 1µF  (hidden comment: C1005X5R1E105K050BC)
CAP, CERM, 1 µF, 25 V,+/- 10%, X5R, 0402; Manufacturer: TDK; Polarized: N; CompType: Capacitor; Value: 1uF; U/M: EA; Cap_F: 0.000001; Tolerance_%: 10; VDC_V: 25; Value2: 25V; TaMin_C: -55; TaMax_C: 80; Cap_Case: 0402; SizeArea_mm2: 0.5; SizeAreaWB_mm2: 3; SizeX_mm: 1; SizeZ_mm: 0.6; AEC Category: Q200; Green_Lifecycle: Active; Green_REACh: Passed
signal-integrity model Cap
simulation model Cap
footprint 0402
footprint 0402M
footprint 0402L
footprint 0402S
pins: 1, 2

## C1005X5R1E224M050BC
designator C?  ValueDisplayed: 0.22µF  (hidden comment: C1005X5R1E224M050BC)
CAP, CERM, 0.22 µF, 25 V,+/- 20%, X5R, 0402; Manufacturer: TDK; Polarized: N; CompType: Capacitor; Value: 0.22uF; U/M: EA; Cap_F: 0.00000022; Tolerance_%: 20; VDC_V: 25; Value2: 25V; TaMin_C: -55; TaMax_C: 85; Cap_Case: 0402; SizeArea_mm2: 0.5; SizeAreaWB_mm2: 3; SizeX_mm: 1; SizeZ_mm: 0.6; AEC Category: Q200
signal-integrity model Cap
simulation model Cap
footprint 0402
footprint 0402M
footprint 0402L
footprint 0402S
pins: 1, 2

## C1005X5R1E225K050BC
designator C?  ValueDisplayed: 2.2µF  (hidden comment: C1005X5R1E225K050BC)
CAP, CERM, 2.2 µF, 25 V,+/- 10%, X5R, 0402; Manufacturer: TDK; Polarized: N; CompType: Capacitor; Value: 2.2uF; U/M: EA; Cap_F: 0.0000022; Tolerance_%: 10; VDC_V: 25; Value2: 25V; TaMin_C: -55; TaMax_C: 85; Cap_Case: 0402; SizeArea_mm2: 0.5; SizeAreaWB_mm2: 3; SizeX_mm: 1; SizeZ_mm: 0.6; AEC Category: Q200; Green_Lifecycle: Active; Green_REACh: Passed
signal-integrity model Cap
simulation model Cap
footprint 0402
footprint 0402M
footprint 0402L
footprint 0402S
pins: 1, 2

## C1005X5R1H104K050BB
designator C?  ValueDisplayed: 0.1µF  (hidden comment: C1005X5R1H104K050BB)
CAP, CERM, 0.1 µF, 50 V,+/- 10%, X5R, 0402; Manufacturer: TDK; Polarized: N; CompType: Capacitor; Value: 0.1uF; U/M: EA; Cap_F: 0.0000001; Tolerance_%: 10; ESR_ohm: 0.039064; Value1: 0.039064 ohm; VDC_V: 50; Value2: 50V; IRMS_A: 0.814669; TaMin_C: -55; TaMax_C: 85; Cap_Case: 0402; SizeArea_mm2: 0.5; SizeAreaWB_mm2: 3; SizeX_mm: 1; SizeZ_mm: 0.6; AEC Category: Q200; Green_Lifecycle: NRND; Green_REACh: Passed
signal-integrity model Cap
simulation model Cap
footprint 0402
footprint 0402M
footprint 0402L
footprint 0402S
pins: 1, 2

## C1005X5R1H473K050BB
designator C?  ValueDisplayed: 0.047µF  (hidden comment: C1005X5R1H473K050BB)
CAP, CERM, 0.047 µF, 50 V,+/- 10%, X5R, 0402; Manufacturer: TDK; Polarized: N; CompType: Capacitor; Value: 0.047uF; U/M: EA; Cap_F: 0.000000047; Tolerance_%: 10; ESR_ohm: 0.06407; Value1: 0.06407 ohm; VDC_V: 50; Value2: 50V; IRMS_A: 0.646122; TaMin_C: -55; TaMax_C: 85; Cap_Case: 0402; SizeArea_mm2: 0.5; SizeAreaWB_mm2: 3; SizeX_mm: 1; SizeZ_mm: 0.6; AEC Category: Q200
signal-integrity model Cap
simulation model Cap
footprint 0402
footprint 0402M
footprint 0402L
footprint 0402S
pins: 1, 2

## C1005X5R1H683K050BB
designator C?  ValueDisplayed: 0.068µF  (hidden comment: C1005X5R1H683K050BB)
CAP, CERM, 0.068 µF, 50 V,+/- 10%, X5R, 0402; Manufacturer: TDK; Polarized: N; CompType: Capacitor; Value: 0.068uF; U/M: EA; Cap_F: 0.000000068; Tolerance_%: 10; ESR_ohm: 0.05606; Value1: 0.05606 ohm; VDC_V: 50; Value2: 50V; IRMS_A: 0.684724; TaMin_C: -55; TaMax_C: 85; Cap_Case: 0402; SizeArea_mm2: 0.5; SizeAreaWB_mm2: 3; SizeX_mm: 1; SizeZ_mm: 0.6; AEC Category: Q200
signal-integrity model Cap
simulation model Cap
footprint 0402
footprint 0402M
footprint 0402L
footprint 0402S
pins: 1, 2

## C1005X5R1V105K050BC
designator C?  ValueDisplayed: 1µF  (hidden comment: C1005X5R1V105K050BC)
CAP, CERM, 1 µF, 35 V,+/- 10%, X5R, 0402; Manufacturer: TDK; Polarized: N; CompType: Capacitor; Value: 1uF; U/M: EA; Cap_F: 0.000001; Tolerance_%: 10; ESR_ohm: 0.011416; Value1: 0.011416 ohm; VDC_V: 35; Value2: 35V; IRMS_A: 1.483; TaMin_C: -55; TaMax_C: 85; Cap_Case: 0402; SizeArea_mm2: 0.5; SizeAreaWB_mm2: 3; SizeX_mm: 1; SizeZ_mm: 0.6; AEC Category: Q200
signal-integrity model Cap
simulation model Cap
footprint 0402
footprint 0402M
footprint 0402L
footprint 0402S
pins: 1, 2

## C1005X5R1V225K050BC
designator C?  ValueDisplayed: 2.2µF  (hidden comment: C1005X5R1V225K050BC)
CAP, CERM, 2.2 µF, 35 V,+/- 10%, X5R, 0402; Manufacturer: TDK; Polarized: N; CompType: Capacitor; Value: 2.2uF; U/M: EA; Cap_F: 0.0000022; Tolerance_%: 10; ESR_ohm: 0.005925; Value1: 0.005925 ohm; VDC_V: 35; Value2: 35V; IRMS_A: 2.05591; TaMin_C: -55; TaMax_C: 85; Cap_Case: 0402; SizeArea_mm2: 0.5; SizeAreaWB_mm2: 3; SizeX_mm: 1; SizeZ_mm: 0.65; AEC Category: Q200
signal-integrity model Cap
simulation model Cap
footprint 0402_065
footprint 0402_065M
footprint 0402_065L
footprint 0402_065S
pins: 1, 2

## C1005X6S0G335K050BC
designator C?  ValueDisplayed: 3.3µF  (hidden comment: C1005X6S0G335K050BC)
CAP, CERM, 3.3 µF, 4 V,+/- 10%, X6S, 0402; Manufacturer: TDK; Polarized: N; CompType: Capacitor; Value: 3.3uF; U/M: EA; Cap_F: 0.0000033; Tolerance_%: 10; ESR_ohm: 0.004157; Value1: 0.004157 ohm; VDC_V: 4; Value2: 4V; IRMS_A: 2.45391; TaMin_C: -55; TaMax_C: 105; Cap_Case: 0402; SizeArea_mm2: 0.5; SizeAreaWB_mm2: 3; SizeX_mm: 1; SizeZ_mm: 0.6; AEC Category: Q200
signal-integrity model Cap
simulation model Cap
footprint 0402
footprint 0402M
footprint 0402L
footprint 0402S
pins: 1, 2

## C1005X6S0G475M050BC
designator C?  ValueDisplayed: 4.7µF  (hidden comment: C1005X6S0G475M050BC)
CAP, CERM, 4.7 µF, 4 V,+/- 20%, X6S, 0402; Manufacturer: TDK; Polarized: N; CompType: Capacitor; Value: 4.7uF; U/M: EA; Cap_F: 0.0000047; Tolerance_%: 20; ESR_ohm: 0.003417; Value1: 0.003417 ohm; VDC_V: 4; Value2: 4V; IRMS_A: 2.7063; TaMin_C: -55; TaMax_C: 105; Cap_Case: 0402; SizeArea_mm2: 0.5; SizeAreaWB_mm2: 3; SizeX_mm: 1; SizeZ_mm: 0.65; AEC Category: Q200
signal-integrity model Cap
simulation model Cap
footprint 0402_065
footprint 0402_065M
footprint 0402_065L
footprint 0402_065S
pins: 1, 2

## C1005X6S1C105K050BC
designator C?  ValueDisplayed: 1µF  (hidden comment: C1005X6S1C105K050BC)
CAP, CERM, 1 µF, 16 V,+/- 10%, X6S, 0402; Manufacturer: TDK; Polarized: N; CompType: Capacitor; Value: 1uF; U/M: EA; Cap_F: 0.000001; Tolerance_%: 10; ESR_ohm: 0.011416; Value1: 0.011416 ohm; VDC_V: 16; Value2: 16V; IRMS_A: 1.483; TaMin_C: -55; TaMax_C: 105; Cap_Case: 0402; SizeArea_mm2: 0.5; SizeAreaWB_mm2: 3; SizeX_mm: 1; SizeZ_mm: 0.6; AEC Category: Q200
signal-integrity model Cap
simulation model Cap
footprint 0402
footprint 0402M
footprint 0402L
footprint 0402S
pins: 1, 2

## C1005X6S1C155K050BC
designator C?  ValueDisplayed: 1.5µF  (hidden comment: C1005X6S1C155K050BC)
CAP, CERM, 1.5 µF, 16 V,+/- 10%, X6S, 0402; Manufacturer: TDK; Polarized: N; CompType: Capacitor; Value: 1.5uF; U/M: EA; Cap_F: 0.0000015; Tolerance_%: 10; ESR_ohm: 0.007753; Value1: 0.007753 ohm; VDC_V: 16; Value2: 16V; IRMS_A: 1.79804; TaMin_C: -55; TaMax_C: 105; Cap_Case: 0402; SizeArea_mm2: 0.5; SizeAreaWB_mm2: 3; SizeX_mm: 1; SizeZ_mm: 0.65; AEC Category: Q200
signal-integrity model Cap
simulation model Cap
footprint 0402_065
footprint 0402_065M
footprint 0402_065L
footprint 0402_065S
pins: 1, 2

## C1005X6S1C225K050BC
designator C?  ValueDisplayed: 2.2µF  (hidden comment: C1005X6S1C225K050BC)
CAP, CERM, 2.2 µF, 16 V,+/- 10%, X6S, 0402; Manufacturer: TDK; Polarized: N; CompType: Capacitor; Value: 2.2uF; U/M: EA; Cap_F: 0.0000022; Tolerance_%: 10; ESR_ohm: 0.005925; Value1: 0.005925 ohm; VDC_V: 16; Value2: 16V; IRMS_A: 2.05591; TaMin_C: -55; TaMax_C: 105; Cap_Case: 0402; SizeArea_mm2: 0.5; SizeAreaWB_mm2: 3; SizeX_mm: 1; SizeZ_mm: 0.65; AEC Category: Q200
signal-integrity model Cap
simulation model Cap
footprint 0402_065
footprint 0402_065M
footprint 0402_065L
footprint 0402_065S
pins: 1, 2

## C1005X6S1H104K050BB
designator C?  ValueDisplayed: 0.1µF  (hidden comment: C1005X6S1H104K050BB)
CAP, CERM, 0.1 µF, 50 V,+/- 10%, X6S, 0402; Manufacturer: TDK; Polarized: N; CompType: Capacitor; Value: 0.1uF; U/M: EA; Cap_F: 0.0000001; Tolerance_%: 10; ESR_ohm: 0.039064; Value1: 0.039064 ohm; VDC_V: 50; Value2: 50V; IRMS_A: 0.814669; TaMin_C: -55; TaMax_C: 105; Cap_Case: 0402; SizeArea_mm2: 0.5; SizeAreaWB_mm2: 3; SizeX_mm: 1; SizeZ_mm: 0.6; AEC Category: Q200
signal-integrity model Cap
simulation model Cap
footprint 0402
footprint 0402M
footprint 0402L
footprint 0402S
pins: 1, 2

## C1005X6S1H473K050BB
designator C?  ValueDisplayed: 0.047µF  (hidden comment: C1005X6S1H473K050BB)
CAP, CERM, 0.047 µF, 50 V,+/- 10%, X6S, 0402; Manufacturer: TDK; Polarized: N; CompType: Capacitor; Value: 0.047uF; U/M: EA; Cap_F: 0.000000047; Tolerance_%: 10; ESR_ohm: 0.06407; Value1: 0.06407 ohm; VDC_V: 50; Value2: 50V; IRMS_A: 0.646122; TaMin_C: -55; TaMax_C: 105; Cap_Case: 0402; SizeArea_mm2: 0.5; SizeAreaWB_mm2: 3; SizeX_mm: 1; SizeZ_mm: 0.6; AEC Category: Q200
signal-integrity model Cap
simulation model Cap
footprint 0402
footprint 0402M
footprint 0402L
footprint 0402S
pins: 1, 2

## C1005X6S1H683K050BB
designator C?  ValueDisplayed: 0.068µF  (hidden comment: C1005X6S1H683K050BB)
CAP, CERM, 0.068 µF, 50 V,+/- 10%, X6S, 0402; Manufacturer: TDK; Polarized: N; CompType: Capacitor; Value: 0.068uF; U/M: EA; Cap_F: 0.000000068; Tolerance_%: 10; ESR_ohm: 0.05606; Value1: 0.05606 ohm; VDC_V: 50; Value2: 50V; IRMS_A: 0.684724; TaMin_C: -55; TaMax_C: 105; Cap_Case: 0402; SizeArea_mm2: 0.5; SizeAreaWB_mm2: 3; SizeX_mm: 1; SizeZ_mm: 0.6; AEC Category: Q200
signal-integrity model Cap
simulation model Cap
footprint 0402
footprint 0402M
footprint 0402L
footprint 0402S
pins: 1, 2

## C1005X7R1C103K050BA
designator C?  ValueDisplayed: 0.01µF  (hidden comment: C1005X7R1C103K050BA)
CAP, CERM, 0.01 µF, 16 V,+/- 10%, X7R, 0402; Manufacturer: TDK; Polarized: N; CompType: Capacitor; Value: 0.01uF; U/M: EA; Cap_F: 0.00000001; Tolerance_%: 10; ESR_ohm: 0.0623; Value1: 0.0623 ohm; VDC_V: 16; Value2: 16V; TaMin_C: -55; TaMax_C: 125; Cap_Case: 0402; SizeArea_mm2: 0.5; SizeAreaWB_mm2: 3; SizeX_mm: 1; SizeZ_mm: 0.6; AEC Category: Q200; Green_Lifecycle: NRND; Green_REACh: Passed
signal-integrity model Cap
simulation model Cap
footprint 0402
footprint 0402M
footprint 0402L
footprint 0402S
pins: 1, 2

## C1005X7R1C224K050BC
designator C?  ValueDisplayed: 0.22µF  (hidden comment: C1005X7R1C224K050BC)
CAP, CERM, 0.22 µF, 16 V,+/- 10%, X7R, 0402; Manufacturer: TDK; Polarized: N; CompType: Capacitor; Value: 0.22uF; U/M: EA; Cap_F: 0.00000022; Tolerance_%: 10; VDC_V: 16; Value2: 16V; TaMin_C: -55; TaMax_C: 125; Cap_Case: 0402; SizeArea_mm2: 0.5; SizeAreaWB_mm2: 3; SizeX_mm: 1; SizeZ_mm: 0.6; AEC Category: Q200; Green_Lifecycle: NRND; Green_REACh: Passed
signal-integrity model Cap
simulation model Cap
footprint 0402
footprint 0402M
footprint 0402L
footprint 0402S
pins: 1, 2

## C1005X7R1C473K050BC
designator C?  ValueDisplayed: 0.047µF  (hidden comment: C1005X7R1C473K050BC)
CAP, CERM, 0.047 µF, 16 V,+/- 10%, X7R, 0402; Manufacturer: TDK; Polarized: N; CompType: Capacitor; Value: 0.047uF; U/M: EA; Cap_F: 0.000000047; Tolerance_%: 10; ESR_ohm: 0.0305; Value1: 0.0305 ohm; VDC_V: 16; Value2: 16V; TaMin_C: -55; TaMax_C: 125; Cap_Case: 0402; SizeArea_mm2: 0.5; SizeAreaWB_mm2: 3; SizeX_mm: 1; SizeZ_mm: 0.6; AEC Category: Q200; Green_Lifecycle: NRND; Green_REACh: Passed
signal-integrity model Cap
simulation model Cap
footprint 0402
footprint 0402M
footprint 0402L
footprint 0402S
pins: 1, 2

## C1005X7R1E104M050BB
designator C?  ValueDisplayed: 0.1µF  (hidden comment: C1005X7R1E104M050BB)
CAP, CERM, 0.1 µF, 25 V,+/- 20%, X7R, 0402; Manufacturer: TDK; Polarized: N; CompType: Capacitor; Value: 0.1uF; U/M: EA; Cap_F: 0.0000001; Tolerance_%: 20; VDC_V: 25; Value2: 25V; TaMin_C: -55; TaMax_C: 125; Cap_Case: 0402; SizeArea_mm2: 0.5; SizeAreaWB_mm2: 3; SizeX_mm: 1; SizeZ_mm: 0.6; AEC Category: Q200; Green_Lifecycle: NRND; Green_REACh: Passed
signal-integrity model Cap
simulation model Cap
footprint 0402
footprint 0402M
footprint 0402L
footprint 0402S
pins: 1, 2

## C1005X7R1H102M050BE
designator C?  ValueDisplayed: 1000pF  (hidden comment: C1005X7R1H102M050BE)
CAP, CERM, 1000 pF, 50 V,+/- 20%, X7R, 0402; Manufacturer: TDK; Polarized: N; CompType: Capacitor; Value: 1000pF; U/M: EA; Cap_F: 0.000000001; Tolerance_%: 20; VDC_V: 50; Value2: 50V; TaMin_C: -55; TaMax_C: 125; Cap_Case: 0402; SizeArea_mm2: 0.5; SizeAreaWB_mm2: 3; SizeX_mm: 1; SizeZ_mm: 0.6; AEC Category: Q200
signal-integrity model Cap
simulation model Cap
footprint 0402
footprint 0402M
footprint 0402L
footprint 0402S
pins: 1, 2

## C1005X7R1H104K050BB
designator C?  ValueDisplayed: 0.1µF  (hidden comment: C1005X7R1H104K050BB)
CAP, CERM, 0.1 µF, 50 V,+/- 10%, X7R, 0402; Manufacturer: TDK; Polarized: N; CompType: Capacitor; Value: 0.1uF; U/M: EA; Cap_F: 0.0000001; Tolerance_%: 10; ESR_ohm: 0.039064; Value1: 0.039064 ohm; VDC_V: 50; Value2: 50V; IRMS_A: 0.814669; TaMin_C: -55; TaMax_C: 125; Cap_Case: 0402; SizeArea_mm2: 0.5; SizeAreaWB_mm2: 3; SizeX_mm: 1; SizeZ_mm: 0.6; AEC Category: Q200; Green_Lifecycle: NRND; Green_REACh: Passed
signal-integrity model Cap
simulation model Cap
footprint 0402
footprint 0402M
footprint 0402L
footprint 0402S
pins: 1, 2

## C1005X7R1H104K050BE
designator C?  ValueDisplayed: 0.1µF  (hidden comment: C1005X7R1H104K050BE)
CAP, CERM, 0.1 µF, 50 V,+/- 10%, X7R, 0402; Manufacturer: TDK; Polarized: N; CompType: Capacitor; Value: 0.1uF; U/M: EA; Cap_F: 0.0000001; Tolerance_%: 10; VDC_V: 50; Value2: 50V; TaMin_C: -55; TaMax_C: 125; Cap_Case: 0402; SizeArea_mm2: 0.5; SizeAreaWB_mm2: 3; SizeX_mm: 1; SizeZ_mm: 0.6; AEC Category: Q200; Green_Lifecycle: Active; Green_REACh: Passed
signal-integrity model Cap
simulation model Cap
footprint 0402
footprint 0402M
footprint 0402L
footprint 0402S
pins: 1, 2

## C1005X7R1H473K050BB
designator C?  ValueDisplayed: 0.047µF  (hidden comment: C1005X7R1H473K050BB)
CAP, CERM, 0.047 µF, 50 V,+/- 10%, X7R, 0402; Manufacturer: TDK; Polarized: N; CompType: Capacitor; Value: 0.047uF; U/M: EA; Cap_F: 0.000000047; Tolerance_%: 10; ESR_ohm: 0.06407; Value1: 0.06407 ohm; VDC_V: 50; Value2: 50V; IRMS_A: 0.646122; TaMin_C: -55; TaMax_C: 125; Cap_Case: 0402; SizeArea_mm2: 0.5; SizeAreaWB_mm2: 3; SizeX_mm: 1; SizeZ_mm: 0.6; AEC Category: Q200; Green_Lifecycle: NRND; Green_REACh: Passed
signal-integrity model Cap
simulation model Cap
footprint 0402
footprint 0402M
footprint 0402L
footprint 0402S
pins: 1, 2

## C1005X7R1H683K050BB
designator C?  ValueDisplayed: 0.068µF  (hidden comment: C1005X7R1H683K050BB)
CAP, CERM, 0.068 µF, 50 V,+/- 10%, X7R, 0402; Manufacturer: TDK; Polarized: N; CompType: Capacitor; Value: 0.068uF; U/M: EA; Cap_F: 0.000000068; Tolerance_%: 10; ESR_ohm: 0.05606; Value1: 0.05606 ohm; VDC_V: 50; Value2: 50V; IRMS_A: 0.684724; TaMin_C: -55; TaMax_C: 125; Cap_Case: 0402; SizeArea_mm2: 0.5; SizeAreaWB_mm2: 3; SizeX_mm: 1; SizeZ_mm: 0.6; AEC Category: Q200; Green_Lifecycle: Active; Green_REACh: Passed
signal-integrity model Cap
simulation model Cap
footprint 0402
footprint 0402M
footprint 0402L
footprint 0402S
pins: 1, 2

## C1005X7S1A105K050BC
designator C?  ValueDisplayed: 1µF  (hidden comment: C1005X7S1A105K050BC)
CAP, CERM, 1 µF, 10 V,+/- 10%, X7S, 0402; Manufacturer: TDK; Polarized: N; CompType: Capacitor; Value: 1uF; U/M: EA; Cap_F: 0.000001; Tolerance_%: 10; ESR_ohm: 0.011416; Value1: 0.011416 ohm; Value2: 10V; IRMS_A: 1.483; TaMin_C: -55; TaMax_C: 125; Cap_Case: 0402; SizeArea_mm2: 0.5; SizeAreaWB_mm2: 3; SizeX_mm: 1; SizeZ_mm: 0.6; AEC Category: Q200; Green_Lifecycle: Active; Green_REACh: Passed
signal-integrity model Cap
simulation model Cap
footprint 0402
footprint 0402M
footprint 0402L
footprint 0402S
pins: 1, 2

## C1005X7S1A155K050BC
designator C?  ValueDisplayed: 1.5µF  (hidden comment: C1005X7S1A155K050BC)
CAP, CERM, 1.5 µF, 10 V,+/- 10%, X7S, 0402; Manufacturer: TDK; Polarized: N; CompType: Capacitor; Value: 1.5uF; U/M: EA; Cap_F: 0.0000015; Tolerance_%: 10; ESR_ohm: 0.00634; Value1: 0.00634 ohm; Value2: 10V; IRMS_A: 1.988475; TaMin_C: -55; TaMax_C: 125; Cap_Case: 0402; SizeArea_mm2: 0.5; SizeAreaWB_mm2: 3; SizeX_mm: 1; SizeZ_mm: 0.65; AEC Category: Q200
signal-integrity model Cap
simulation model Cap
footprint 0402_065
footprint 0402_065M
footprint 0402_065L
footprint 0402_065S
pins: 1, 2

## C1005X7S1A225K050BC
designator C?  ValueDisplayed: 2.2µF  (hidden comment: C1005X7S1A225K050BC)
CAP, CERM, 2.2 µF, 10 V,+/- 10%, X7S, 0402; Manufacturer: TDK; Polarized: N; CompType: Capacitor; Value: 2.2uF; U/M: EA; Cap_F: 0.0000022; Tolerance_%: 10; ESR_ohm: 0.005925; Value1: 0.005925 ohm; Value2: 10V; IRMS_A: 2.05591; TaMin_C: -55; TaMax_C: 125; Cap_Case: 0402; SizeArea_mm2: 0.5; SizeAreaWB_mm2: 3; SizeX_mm: 1; SizeZ_mm: 0.65; AEC Category: Q200
signal-integrity model Cap
simulation model Cap
footprint 0402_065
footprint 0402_065M
footprint 0402_065L
footprint 0402_065S
pins: 1, 2

## C1206C101JCGACTU
designator C?  ValueDisplayed: 100pF  (hidden comment: C1206C101JCGACTU)
CAP, CERM, 100 pF, 500 V,+/- 5%, C0G/NP0, 1206; Manufacturer: Kemet; Polarized: N; CompType: Capacitor; Value: 100pF; U/M: EA; Cap_F: 0.0000000001; Tolerance_%: 5; VDC_V: 500; Value2: 500V; TaMin_C: -55; TaMax_C: 125; Cap_Case: 1206; SizeArea_mm2: 5.12; SizeAreaWB_mm2: 10.92; SizeX_mm: 3.2; SizeY_mm: 1.6; SizeZ_mm: 1.35; AEC Category: Q200; Green_Lifecycle: Active; Green_REACh: Passed
signal-integrity model Cap
simulation model Cap
footprint 1206
footprint 1206M
footprint 1206L
pins: 1, 2

## C1206C102K5RACTU
designator C?  ValueDisplayed: 1000pF  (hidden comment: C1206C102K5RACTU)
CAP, CERM, 1000 pF, 50 V,+/- 10%, X7R, 1206; Manufacturer: Kemet; Polarized: N; CompType: Capacitor; Value: 1000pF; U/M: EA; Cap_F: 0.000000001; Tolerance_%: 10; ESR_ohm: 0.426; Value1: 0.426 ohm; VDC_V: 50; Value2: 50V; IRMS_A: 0.189; TaMin_C: -55; TaMax_C: 125; Cap_Case: 1206; SizeArea_mm2: 5.12; SizeAreaWB_mm2: 10.92; SizeX_mm: 3.2; SizeY_mm: 1.6; SizeZ_mm: 1.35; AEC Category: Q200; Green_Lifecycle: Active; Green_REACh: Passed
signal-integrity model Cap
simulation model Cap
footprint 1206
footprint 1206M
footprint 1206L
pins: 1, 2

## C1206C102KCRACTU
designator C?  ValueDisplayed: 1000pF  (hidden comment: C1206C102KCRACTU)
CAP, CERM, 1000 pF, 500 V,+/- 10%, X7R, 1206; Manufacturer: Kemet; Polarized: N; CompType: Capacitor; Value: 1000pF; U/M: EA; Cap_F: 0.000000001; Tolerance_%: 10; VDC_V: 500; Value2: 500V; TaMin_C: -55; TaMax_C: 125; Cap_Case: 1206; SizeArea_mm2: 5.12; SizeAreaWB_mm2: 10.92; SizeX_mm: 3.2; SizeY_mm: 1.6; SizeZ_mm: 1.9; AEC Category: Q200; Green_Lifecycle: Active; Green_REACh: Passed
signal-integrity model Cap
simulation model Cap
footprint 1206_190
footprint 1206_190M
footprint 1206_190L
pins: 1, 2

## C1206C102KGRACAUTO
designator C?  ValueDisplayed: 1000pF  (hidden comment: C1206C102KGRACAUTO)
CAP, CERM, 1000 pF, 2000 V,+/- 10%, X7R, AEC-Q200 Grade 1, 1206; Manufacturer: Kemet; Polarized: N; CompType: Capacitor; Value: 1000pF; U/M: EA; Cap_F: 0.000000001; Tolerance_%: 10; VDC_V: 2000; Value2: 2000V; TaMin_C: -55; TaMax_C: 125; Cap_Case: 1206; SizeArea_mm2: 5.12; SizeAreaWB_mm2: 10.92; SizeX_mm: 3.2; SizeY_mm: 1.6; SizeZ_mm: 1.8; AEC Category: Q200; AEC Qualified: Y; AEC Grade: 1
signal-integrity model Cap
simulation model Cap
footprint 1206_180
footprint 1206_180M
footprint 1206_180L
pins: 1, 2

## C1206C103J2GACAUTO
designator C?  ValueDisplayed: 0.01µF  (hidden comment: C1206C103J2GACAUTO)
CAP, CERM, 0.01 µF, 200 V,+/- 5%, C0G/NP0, AEC-Q200 Grade 1, 1206; Manufacturer: Kemet; Polarized: N; CompType: Capacitor; Value: 0.01uF; U/M: EA; Cap_F: 0.00000001; Tolerance_%: 5; VDC_V: 200; Value2: 200V; TaMin_C: -55; TaMax_C: 125; Cap_Case: 1206; SizeArea_mm2: 5.12; SizeAreaWB_mm2: 10.92; SizeX_mm: 3.2; SizeY_mm: 1.6; SizeZ_mm: 1.35; AEC Category: Q200; AEC Qualified: Y; AEC Grade: 1; Green_Lifecycle: Not Set; Green_REACh: Incomplete
signal-integrity model Cap
simulation model Cap
footprint 1206
footprint 1206M
footprint 1206L
pins: 1, 2

## C1206C103J5RACTU
designator C?  ValueDisplayed: 0.01µF  (hidden comment: C1206C103J5RACTU)
CAP, CERM, 0.01 µF, 50 V,+/- 5%, X7R, 1206; Manufacturer: Kemet; Polarized: N; CompType: Capacitor; Value: 0.01uF; U/M: EA; Cap_F: 0.00000001; Tolerance_%: 5; ESR_ohm: 0.155; Value1: 0.155 ohm; VDC_V: 50; Value2: 50V; IRMS_A: 0.416; TaMin_C: -55; TaMax_C: 125; Cap_Case: 1206; SizeArea_mm2: 5.12; SizeAreaWB_mm2: 10.92; SizeX_mm: 3.2; SizeY_mm: 1.6; SizeZ_mm: 1.35; AEC Category: Q200; Green_Lifecycle: Active; Green_REACh: Passed
signal-integrity model Cap
simulation model Cap
footprint 1206
footprint 1206M
footprint 1206L
pins: 1, 2

## C1206C103K5RACTU
designator C?  ValueDisplayed: 0.01µF  (hidden comment: C1206C103K5RACTU)
CAP, CERM, 0.01 µF, 50 V,+/- 10%, X7R, 1206; Manufacturer: Kemet; Polarized: N; CompType: Capacitor; Value: 0.01uF; U/M: EA; Cap_F: 0.00000001; Tolerance_%: 10; ESR_ohm: 0.155; Value1: 0.155 ohm; VDC_V: 50; Value2: 50V; IRMS_A: 0.416; TaMin_C: -55; TaMax_C: 125; Cap_Case: 1206; SizeArea_mm2: 5.12; SizeAreaWB_mm2: 10.92; SizeX_mm: 3.2; SizeY_mm: 1.6; SizeZ_mm: 1.35; AEC Category: Q200; Green_Lifecycle: Not Set; Green_REACh: Incomplete
signal-integrity model Cap
simulation model Cap
footprint 1206
footprint 1206M
footprint 1206L
pins: 1, 2

## C1206C103KARACTU
designator C?  ValueDisplayed: 0.01µF  (hidden comment: C1206C103KARACTU)
CAP, CERM, 0.01 µF, 250 V,+/- 10%, X7R, 1206; Manufacturer: Kemet; Polarized: N; CompType: Capacitor; Value: 0.01uF; U/M: EA; Cap_F: 0.00000001; Tolerance_%: 10; VDC_V: 250; Value2: 250V; TaMin_C: -55; TaMax_C: 125; Cap_Case: 1206; SizeArea_mm2: 5.12; SizeAreaWB_mm2: 10.92; SizeX_mm: 3.2; SizeY_mm: 1.6; SizeZ_mm: 1.35; AEC Category: Q200; Green_Lifecycle: Active; Green_REACh: Passed
signal-integrity model Cap
simulation model Cap
footprint 1206
footprint 1206M
footprint 1206L
pins: 1, 2

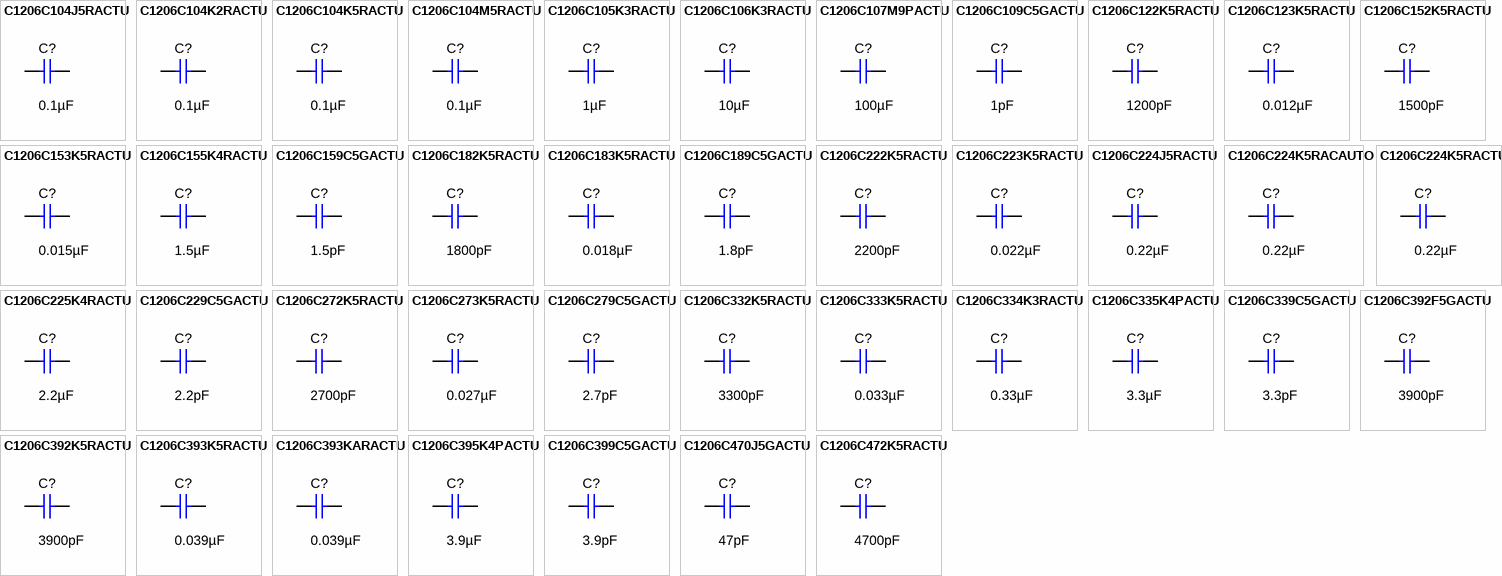
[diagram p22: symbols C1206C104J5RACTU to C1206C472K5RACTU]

## C1206C104J5RACTU
designator C?  ValueDisplayed: 0.1µF  (hidden comment: C1206C104J5RACTU)
CAP, CERM, 0.1 µF, 50 V,+/- 5%, X7R, 1206; Manufacturer: Kemet; Polarized: N; CompType: Capacitor; Value: 0.1uF; U/M: EA; Cap_F: 0.0000001; Tolerance_%: 5; ESR_ohm: 0.059; Value1: 0.059 ohm; VDC_V: 50; Value2: 50V; IRMS_A: 1.2; TaMin_C: -55; TaMax_C: 125; Cap_Case: 1206; SizeArea_mm2: 5.12; SizeAreaWB_mm2: 10.92; SizeX_mm: 3.2; SizeY_mm: 1.6; SizeZ_mm: 1.35; AEC Category: Q200; Green_Lifecycle: Active; Green_REACh: Passed
signal-integrity model Cap
simulation model Cap
footprint 1206
footprint 1206M
footprint 1206L
pins: 1, 2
